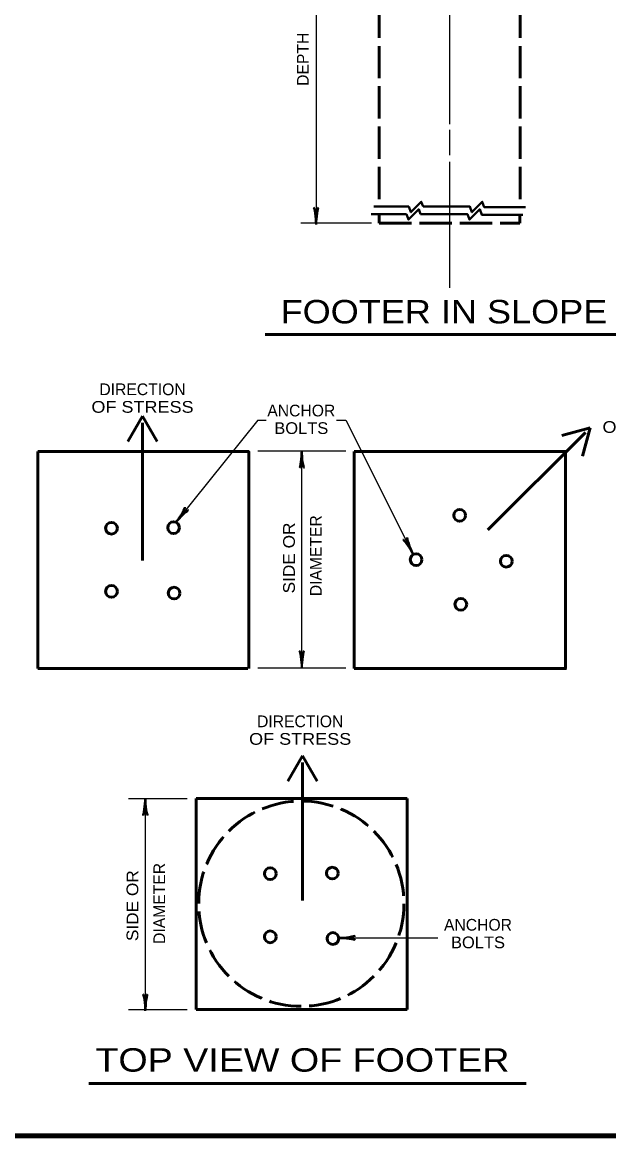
# Model space of a CAD drawing. Extents: x -711 to 145, y 25 to 569.
# Drawn here: x -515 to -395, y 36.6 to 264.5 of the extents above; entities that cross this region are included whole.
import ezdxf
from ezdxf.enums import TextEntityAlignment as Align

# ---------------------------------------------------------------- set-up
doc = ezdxf.new("R2010")
doc.units = 0
doc.header["$LTSCALE"] = 1.1
doc.linetypes.add('LONG_DASHED', pattern=[7.5, 6, -1.5])
doc.layers.add('1', color=7, linetype='Continuous', lineweight=53)

msp = doc.modelspace()

# ---------------------------------------------------------------- linework, layer by layer
at = {"layer": '1', "linetype": 'LONG_DASHED'}
for p, q in [((-441.956, 292.637), (-441.956, 226.756)), ((-413.156, 292.637), (-413.156, 226.637)), ((-441.974, 225.174), (-441.974, 223.374)), ((-441.974, 223.374), (-413.174, 223.374)), ((-413.174, 225.174), (-413.174, 223.374))]:
    msp.add_line(p, q, dxfattribs=at)
at = {"layer": '1', "lineweight": 25}
for p, q in [((-454.895, 286.689), (-454.895, 223.126)), ((-427.556, 243.608), (-427.556, 273.241)), ((-427.556, 237.275), (-427.556, 242.477)), ((-427.556, 210.13), (-427.556, 235.917)), ((-443.585, 223.352), (-457.985, 223.352)), ((-466.817, 183.059), (-483.523, 162.233)), ((-466.817, 183.059), (-465.101, 183.059)), ((-450.684, 183.059), (-448.817, 183.059)), ((-448.817, 183.059), (-435.122, 155.711)), ((-466.817, 176.765), (-448.817, 176.765)), ((-457.817, 132.365), (-457.817, 176.765)), ((-493.279, 105.612), (-481.279, 105.612)), ((-489.846, 105.612), (-489.846, 62.131)), ((-457.833, 105.581), (-457.833, 91.164)), ((-450.37, 77.063), (-429.97, 77.063)), ((-493.279, 62.412), (-481.279, 62.412))]:
    msp.add_line(p, q, dxfattribs=at)
at = {"layer": '1', "lineweight": 40}
for p, q in [((-443.104, 226.756), (-435.904, 226.756)), ((-443.613, 225.229), (-436.413, 225.229))]:
    msp.add_line(p, q, dxfattribs=at)
at = {"layer": '1'}
for p, q in [((-465.3, 200.556), (-391.648, 200.556)), ((-490.389, 183.887), (-493.389, 178.691)), ((-490.389, 183.887), (-487.389, 178.691)), ((-490.389, 182.514), (-490.389, 154.314)), ((-419.726, 160.574), (-399.786, 180.514)), ((-398.823, 181.455), (-404.619, 179.902)), ((-398.823, 181.455), (-400.376, 175.659)), ((-447.071, 176.606), (-447.071, 132.206)), ((-447.071, 176.606), (-403.871, 176.606)), ((-403.871, 176.606), (-403.871, 132.206)), ((-447.071, 132.206), (-403.627, 132.206)), ((-457.663, 114.317), (-460.663, 109.121)), ((-457.663, 114.317), (-454.663, 109.121)), ((-457.663, 112.944), (-457.663, 84.744)), ((-479.433, 105.581), (-436.233, 105.581)), ((-479.433, 105.581), (-479.433, 62.381)), ((-436.233, 105.581), (-436.233, 62.381)), ((-479.433, 62.381), (-436.233, 62.381)), ((-501.403, 47.285), (-411.923, 47.285))]:
    msp.add_line(p, q, dxfattribs=at)
at = {"layer": '1', "lineweight": 158}
msp.add_line((138.105, 36.575), (-653.495, 36.575), dxfattribs=at)
at = {"layer": '1', "lineweight": 40}
for points in [[(-436.413, 225.229), (-436.003, 224.102), (-433.882, 226.223), (-433.52, 225.229)], [(-435.904, 226.756), (-435.494, 225.628), (-433.373, 227.75), (-433.011, 226.756)], [(-433.52, 225.229), (-423.92, 225.229), (-423.509, 224.102), (-421.388, 226.223), (-420.978, 225.095), (-412.578, 225.095)], [(-433.011, 226.756), (-423.411, 226.756), (-423.001, 225.628), (-420.879, 227.75), (-420.469, 226.622), (-412.069, 226.622)]]:
    msp.add_lwpolyline(points, dxfattribs=at)
at = {"layer": '1'}
for points in [[(-511.871, 176.606), (-511.871, 154.406), (-511.871, 132.206)], [(-511.871, 176.606), (-490.355, 176.606), (-468.671, 176.606), (-468.671, 154.406), (-468.671, 132.206)], [(-511.871, 132.206), (-490.355, 132.206), (-468.839, 132.206)]]:
    msp.add_lwpolyline(points, dxfattribs=at)
at = {"layer": '1', "lineweight": 25}
msp.add_lwpolyline([(-466.817, 132.365), (-457.778, 132.365), (-448.817, 132.365)], dxfattribs=at)
at = {"layer": '1'}
for centre in [(-425.522, 163.563), (-496.768, 160.93), (-484.067, 161.044), (-434.422, 154.501), (-415.975, 154.177), (-496.768, 148), (-483.952, 147.656), (-425.279, 145.358), (-464.271, 90.216), (-451.57, 90.33), (-464.271, 77.286), (-451.456, 76.943)]:
    msp.add_circle(centre, 1.2, dxfattribs=at)
at = {"layer": '1', "linetype": 'LONG_DASHED'}
msp.add_circle((-457.922, 84.071), 21, dxfattribs=at)
at = {"layer": '1', "lineweight": 40}
for centre, major_axis, ratio, start_param, end_param in [((-455.227, 224.435), (0.187, -2.143), 0.122415, 0.8963533, 3.1415927), ((-454.641, 224.47), (0.211, 2.108), 0.07063, 6.2823074, 8.5597026), ((-458.071, 175.421), (-0.211, -2.108), 0.07063, 6.2823074, 8.5597026), ((-457.486, 175.456), (-0.187, 2.143), 0.122415, 0.8963533, 3.1415927), ((-482.963, 163.462), (-1.195, -1.789), 0.122415, 0.8963533, 3.1415927), ((-482.484, 163.123), (-1.483, -1.512), 0.07063, 3.1407148, 5.41811), ((-436.005, 156.734), (1.127, -1.832), 0.122415, 0.8963533, 3.1415927), ((-435.497, 157.027), (-0.755, 1.979), 0.07063, 6.2823074, 8.5597026), ((-458.149, 133.675), (0.187, -2.143), 0.122415, 0.8963533, 3.1415927), ((-457.564, 133.71), (0.211, 2.108), 0.07063, 6.2823074, 8.5597026), ((-490.1, 104.267), (-0.211, -2.108), 0.07063, 6.2823074, 8.5597026), ((-489.514, 104.303), (-0.187, 2.143), 0.122415, 0.8963533, 3.1415927), ((-449.06, 77.395), (-2.143, -0.187), 0.122415, 0.8963533, 3.1415927), ((-449.025, 76.809), (2.108, -0.211), 0.07063, 6.2823074, 8.5597026), ((-490.178, 63.44), (0.187, -2.143), 0.122415, 0.8963533, 3.1415927), ((-489.592, 63.476), (0.211, 2.108), 0.07063, 6.2823074, 8.5597026)]:
    msp.add_ellipse(centre, major_axis=major_axis, ratio=ratio, start_param=start_param, end_param=end_param, dxfattribs=at)

# ---------------------------------------------------------------- texts
at = {"layer": '1'}
for s, p in [('DEPTH', (-456.41, 256.916)), ('DIAMETER', (-453.747, 155.302)), ('DIAMETER', (-485.785, 84.13))]:
    msp.add_text(s, height=2.4, rotation=90, dxfattribs=at).set_placement(p, align=Align.CENTER)
for s, height, width, p in [('FOOTER IN SLOPE', 4.8, 1.15, (-428.731, 202.86)), ('OF STRESS', 2.4, 1.15, (-490.418, 184.569)), ('BOLTS', 2.4, 1.05, (-457.922, 180.221)), ('OF STRESS', 2.4, 1.15, (-385.834, 180.45)), ('OF STRESS', 2.4, 1.15, (-458.151, 116.601)), ('BOLTS', 2.4, 1.05, (-421.763, 74.951)), ('TOP VIEW OF FOOTER', 4.8, 1.2, (-457.693, 49.691))]:
    msp.add_text(s, height=height, dxfattribs=dict(at, width=width)).set_placement(p, align=Align.CENTER)
for s, p in [('DIRECTION', (-490.418, 188.169)), ('ANCHOR', (-457.922, 183.821)), ('DIRECTION', (-458.151, 120.201)), ('ANCHOR', (-421.763, 78.551))]:
    msp.add_text(s, height=2.4, dxfattribs=at).set_placement(p, align=Align.CENTER)
at = {"layer": '1', "width": 1.1}
for p in [(-459.239, 154.844), (-491.278, 83.672)]:
    msp.add_text('SIDE OR', height=2.4, rotation=90, dxfattribs=at).set_placement(p, align=Align.CENTER)

doc.saveas('drawing.dxf')
